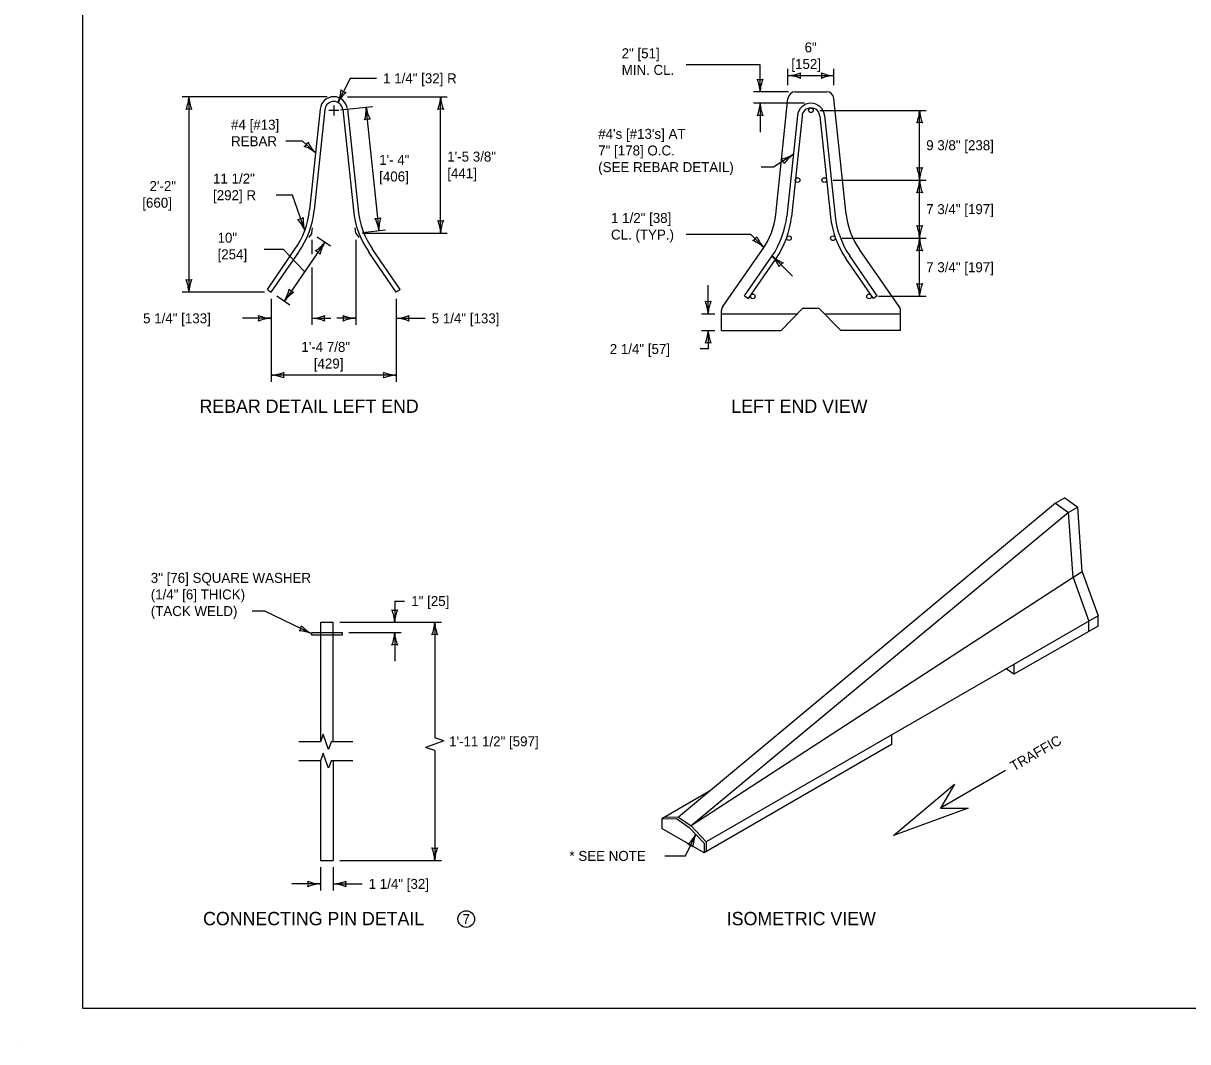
# Model space of a CAD drawing. Extents: x 49991.4 to 50021, y 49987.6 to 50011.4.
# Drawn here: x 49999.02 to 50006.04, y 49987.6 to 49993.73 of the extents above; entities that cross this region are included whole.
import ezdxf

# ---------------------------------------------------------------- set-up
doc = ezdxf.new("R2010")
doc.units = 0
for name, color, linetype in [('Level 1', 7, 'Continuous'), ('Level 2', 7, 'Continuous'), ('Level 3', 7, 'Continuous'), ('Level 4', 7, 'Continuous'), ('Level 6', 7, 'Continuous')]:
    doc.layers.add(name, color=color, linetype=linetype)

msp = doc.modelspace()

# ---------------------------------------------------------------- linework, layer by layer
at = {"layer": 'Level 1'}
for p, q in [((50003.5549, 49992.5777), (50003.6287, 49993.2762)), ((50003.6726, 49993.3157), (50003.8618, 49993.3157)), ((50003.9796, 49992.5777), (50003.9058, 49993.2762)), ((50000.8121, 49993.2116), (50000.7483, 49992.6061)), ((50000.8402, 49993.2089), (50000.7764, 49992.6032)), ((50000.948, 49993.2089), (50001.0118, 49992.6032)), ((50000.9762, 49993.2116), (50001.0399, 49992.6061)), ((50003.6852, 49993.1724), (50003.6215, 49992.5668)), ((50003.7133, 49993.1696), (50003.6496, 49992.5639)), ((50003.8211, 49993.1696), (50003.8849, 49992.5639)), ((50003.8493, 49993.1724), (50003.913, 49992.5669)), ((50000.4945, 49992.1265), (50000.6603, 49992.3677)), ((50001.2936, 49992.1265), (50001.1279, 49992.3677)), ((50003.2359, 49992.024), (50003.4758, 49992.3662)), ((50004.2985, 49992.024), (50004.0587, 49992.3662)), ((50000.5177, 49992.1104), (50000.6836, 49992.3516)), ((50001.2703, 49992.1104), (50001.1046, 49992.3516)), ((50003.3677, 49992.0871), (50003.5334, 49992.3283)), ((50003.391, 49992.0711), (50003.5567, 49992.3124)), ((50004.1436, 49992.0711), (50003.9777, 49992.3124)), ((50004.1667, 49992.0871), (50004.001, 49992.3284)), ((50000.4945, 49992.1265), (50000.5177, 49992.1104)), ((50001.2936, 49992.1265), (50001.2703, 49992.1104)), ((50003.3677, 49992.0871), (50003.391, 49992.0711)), ((50004.1667, 49992.0871), (50004.1436, 49992.0711)), ((50003.5868, 49991.8782), (50003.7191, 49992.0126)), ((50003.7191, 49992.0126), (50003.8152, 49992.0126)), ((50003.9475, 49991.8782), (50003.8152, 49992.0126)), ((50003.2279, 49991.8782), (50003.2279, 49991.9986)), ((50004.3064, 49991.8782), (50004.3065, 49991.9986)), ((50003.2279, 49991.8782), (50003.5868, 49991.8782)), ((50004.3064, 49991.8782), (50003.9475, 49991.8782)), ((50005.2397, 49990.8408), (50002.9697, 49988.9511)), ((50005.2953, 49990.8729), (50005.2397, 49990.8408)), ((50005.2397, 49990.8408), (50005.3181, 49990.7846)), ((50005.2953, 49990.8729), (50005.3736, 49990.8168)), ((50005.3181, 49990.7846), (50003.0452, 49988.897)), ((50005.3736, 49990.8168), (50005.3181, 49990.7846)), ((50005.3451, 49990.3934), (50005.3181, 49990.7846)), ((50005.4006, 49990.4264), (50005.3736, 49990.8168)), ((50005.4006, 49990.4264), (50005.3451, 49990.3934)), ((50005.4006, 49990.4264), (50005.4957, 49990.1624)), ((50005.3451, 49990.3934), (50003.0452, 49988.897)), ((50005.3451, 49990.3934), (50005.4402, 49990.1304)), ((50000.8143, 49990.1227), (50000.8143, 49989.4034)), ((50000.8905, 49990.1227), (50000.8143, 49990.1227)), ((50000.8905, 49989.4034), (50000.8905, 49990.1227)), ((50005.4957, 49990.1624), (50003.1363, 49988.8014)), ((50005.4402, 49990.0674), (50005.4402, 49990.1304)), ((50005.4957, 49990.0989), (50005.4957, 49990.1624)), ((50000.7611, 49990.0618), (50000.9439, 49990.0618)), ((50000.7611, 49990.0465), (50000.7611, 49990.0618)), ((50000.9439, 49990.0465), (50000.7611, 49990.0465)), ((50000.9439, 49990.0618), (50000.9439, 49990.0465)), ((50005.4957, 49990.0989), (50004.9887, 49989.8113)), ((50004.9887, 49989.8113), (50004.9434, 49989.8438)), ((50004.9887, 49989.87), (50004.9887, 49989.8113)), ((50004.2529, 49989.4455), (50004.2529, 49989.3874)), ((50004.2529, 49989.3874), (50003.1233, 49988.7352)), ((50000.8143, 49989.29), (50000.8143, 49988.6899)), ((50000.8905, 49989.29), (50000.8905, 49988.6899)), ((50004.9391, 49989.2312), (50004.5477, 49989.0052)), ((50004.9393, 49989.2308), (50004.5479, 49989.0049)), ((50003.1563, 49989.1065), (50002.869, 49988.9406)), ((50002.869, 49988.9406), (50002.9584, 49988.9417)), ((50002.869, 49988.9406), (50002.869, 49988.882)), ((50002.9697, 49988.9511), (50002.8827, 49988.9485)), ((50002.9584, 49988.9417), (50003.034, 49988.8875)), ((50002.9697, 49988.9511), (50003.0452, 49988.897)), ((50003.1233, 49988.7352), (50002.869, 49988.882)), ((50003.034, 49988.8875), (50003.1233, 49988.7938)), ((50003.0452, 49988.897), (50003.1363, 49988.8014)), ((50003.1233, 49988.7938), (50003.1233, 49988.7352)), ((50003.1363, 49988.8014), (50003.1363, 49988.7427)), ((50000.8143, 49988.6899), (50000.8905, 49988.6899)), ((49999.0245, 49987.5988), (49999.0245, 49987.5988))]:
    msp.add_line(p, q, dxfattribs=at)
for points in [[(49999.3835, 49998.9992), (50016.7501, 49998.9992), (50016.7501, 49987.7988), (49999.3835, 49987.7988)], [(50004.7147, 49989.0049), (50004.2635, 49988.8407), (50004.6311, 49989.1497), (50004.5481, 49989.005)]]:
    msp.add_lwpolyline(points, close=True, dxfattribs=at)
for centre in [(50003.7672, 49993.2044), (50003.687, 49992.7844), (50003.8475, 49992.7844), (50003.6348, 49992.4349), (50003.8997, 49992.4346), (50003.4172, 49992.0843), (50004.1174, 49992.0842)]:
    msp.add_circle(centre, 0.0141, dxfattribs=at)
for centre, radius, start, end in [((50000.8941, 49993.2036), 0.0824, 5.57877, 174.42123), ((50003.6726, 49993.2715), 0.0442, 90, 173.97247), ((50003.8618, 49993.2715), 0.0442, 6.02753, 90), ((50000.8941, 49993.2036), 0.0542, 5.57877, 174.42123), ((50003.7672, 49993.1643), 0.0824, 5.57877, 174.42123), ((50003.7672, 49993.1643), 0.0542, 5.57877, 174.42123), ((50000.2348, 49992.6602), 0.5163, 325.491, 353.991), ((50000.2348, 49992.6602), 0.5446, 325.491, 353.991), ((50001.5534, 49992.6602), 0.5446, 186.009, 214.509), ((50001.5534, 49992.6602), 0.5163, 186.009, 214.509), ((50003.1065, 49992.625), 0.4509, 324.97771, 353.97247), ((50004.4279, 49992.625), 0.4509, 186.02753, 215.02228), ((50003.108, 49992.6209), 0.5163, 325.47387, 353.982), ((50003.108, 49992.6209), 0.5446, 325.491, 353.991), ((50004.4265, 49992.6209), 0.5446, 186.009, 214.509), ((50004.4265, 49992.6209), 0.5163, 186.009, 214.509), ((50003.2721, 49991.9986), 0.0442, 144.97771, 180), ((50004.2623, 49991.9986), 0.0442, 0, 35.02229)]:
    msp.add_arc(centre, radius, start, end, dxfattribs=at)
at = {"layer": 'Level 2'}
msp.add_ellipse((50001.6917, 49988.3367), major_axis=(0.05, 0), ratio=0.9994, dxfattribs=at)
at = {"layer": 'Level 3'}
for p, q in [((50003.4611, 49993.4777), (50003.0164, 49993.4777)), ((50003.4611, 49993.3157), (50003.4611, 49993.4777)), ((50003.6287, 49993.3557), (50003.6287, 49993.4532)), ((50003.6287, 49993.4132), (50003.9058, 49993.4132)), ((50003.9058, 49993.3557), (50003.9058, 49993.4532)), ((50000.9929, 49993.3968), (50000.9188, 49993.2518)), ((50001.1509, 49993.3968), (50000.9929, 49993.3968)), ((50000.8541, 49993.2861), (49999.9815, 49993.2861)), ((50000.0215, 49993.2861), (50000.0215, 49992.1104)), ((50000.9764, 49993.2861), (50001.5774, 49993.2861)), ((50001.5374, 49992.4655), (50001.5374, 49993.2861)), ((50003.6326, 49993.3157), (50003.4211, 49993.3157)), ((50000.9241, 49993.2036), (50000.8641, 49993.2036)), ((50000.8941, 49993.2336), (50000.8941, 49993.1736)), ((50000.9339, 49993.2078), (50001.1282, 49993.2283)), ((50001.1665, 49992.4803), (50001.0885, 49993.2241)), ((50003.7273, 49993.2468), (50003.4211, 49993.2468)), ((50003.4611, 49993.2468), (50003.4611, 49993.0734)), ((50003.8214, 49993.2042), (50004.4611, 49993.2042)), ((50004.4211, 49992.7844), (50004.4211, 49993.2042)), ((50000.7058, 49993.0182), (50000.6051, 49993.0182)), ((50000.7058, 49993.0182), (50000.7844, 49992.9494)), ((50003.6606, 49992.9384), (50003.5407, 49992.8626)), ((50003.5407, 49992.8626), (50003.4669, 49992.8626)), ((50003.9017, 49992.7844), (50004.4611, 49992.7844)), ((50004.4211, 49992.4349), (50004.4211, 49992.7844)), ((50000.6453, 49992.6935), (50000.5476, 49992.6935)), ((50000.7192, 49992.4814), (50000.6453, 49992.6935)), ((50000.7626, 49992.4655), (50000.7446, 49992.4395)), ((50000.7626, 49992.4655), (50000.7658, 49992.4962)), ((50000.7948, 49992.4429), (50000.8737, 49992.3887)), ((50001.0262, 49992.4655), (50001.023, 49992.4962)), ((50001.0262, 49992.4655), (50001.0442, 49992.4395)), ((50001.066, 49992.4696), (50001.2063, 49992.4845)), ((50001.0662, 49992.4655), (50001.5774, 49992.4655)), ((50003.4055, 49992.4563), (50003.0165, 49992.4563)), ((50003.4838, 49992.378), (50003.4055, 49992.4563)), ((50003.9547, 49992.4349), (50004.4611, 49992.4349)), ((50004.4211, 49992.0852), (50004.4211, 49992.4349)), ((50000.8407, 49992.4114), (50000.5965, 49992.0562)), ((50000.7626, 49992.4255), (50000.7626, 49992.3378)), ((50001.0262, 49992.4255), (50001.0262, 49991.9126)), ((50003.5334, 49992.3284), (50003.6561, 49992.2058)), ((50000.7625, 49992.2576), (50000.7626, 49991.9126)), ((50003.1481, 49991.9789), (50003.1481, 49992.1523)), ((50000.4777, 49992.1104), (49999.9815, 49992.1104)), ((50000.5506, 49992.0877), (50000.6295, 49992.0336)), ((50004.1739, 49992.0852), (50004.4611, 49992.0852)), ((50000.5177, 49992.0704), (50000.5177, 49991.5704)), ((50001.2703, 49992.0704), (50001.2703, 49991.5704)), ((50000.5177, 49991.9526), (50000.3443, 49991.9526)), ((50000.7626, 49991.9526), (50000.876, 49991.9526)), ((50001.0262, 49991.9526), (50000.9128, 49991.9526)), ((50001.2703, 49991.9526), (50001.4438, 49991.9526)), ((50003.1081, 49991.9789), (50003.1879, 49991.9789)), ((50003.1081, 49991.8782), (50003.1879, 49991.8782)), ((50003.1481, 49991.8782), (50003.1481, 49991.7679)), ((50003.1481, 49991.7679), (50003.1002, 49991.7679)), ((50001.2703, 49991.6104), (50000.5177, 49991.6104)), ((50000.4787, 49990.1904), (50000.4033, 49990.1904)), ((50000.7611, 49990.0541), (50000.4787, 49990.1904)), ((50001.2607, 49990.2507), (50001.2607, 49990.1228)), ((50001.2607, 49990.2507), (50001.3207, 49990.2507)), ((50000.9305, 49990.1228), (50001.5421, 49990.1228)), ((50001.5021, 49990.1228), (50001.5021, 49989.4286)), ((50000.9839, 49990.0618), (50001.3007, 49990.0618)), ((50001.2607, 49990.0618), (50001.2607, 49989.8884)), ((50001.5567, 49989.4092), (50001.5021, 49989.4286)), ((50001.5021, 49989.3898), (50001.4471, 49989.3703)), ((50001.5021, 49989.3509), (50001.4471, 49989.3703)), ((50001.5567, 49989.4092), (50001.5021, 49989.3898)), ((50001.5021, 49989.3509), (50001.5021, 49988.6899)), ((50003.0116, 49988.717), (50003.073, 49988.8466)), ((50002.8864, 49988.7171), (50003.0114, 49988.7171)), ((50000.8143, 49988.6499), (50000.8143, 49988.5086)), ((50000.8905, 49988.6499), (50000.8905, 49988.5086)), ((50000.9305, 49988.6899), (50001.5421, 49988.6899)), ((50000.8143, 49988.5486), (50000.6409, 49988.5486)), ((50000.8905, 49988.5486), (50001.064, 49988.5486))]:
    msp.add_line(p, q, dxfattribs=at)
msp.add_lwpolyline([(50000.7187, 49992.2338), (50000.5922, 49992.3675), (50000.4746, 49992.3675)], dxfattribs=at)
for centre, radius, start, end in [((50003.6172, 49993.6459), 0.233, 272.82731, 292.07716), ((50003.6195, 49993.191), 0.2224, 67.45601, 87.63952), ((50003.7569, 49993.4132), 0.0548, 162.13882, 197.86118), ((50003.915, 49993.6353), 0.2223, 247.45601, 267.63952), ((50003.7776, 49993.4132), 0.0548, 342.13882, 17.86118), ((50003.9173, 49993.1804), 0.233, 92.82731, 112.07716), ((50003.4611, 49993.444), 0.0548, 252.13882, 287.86118), ((50003.2284, 49993.3043), 0.233, 2.82731, 22.07716), ((50003.6832, 49993.3066), 0.2223, 157.45601, 177.63952), ((49999.7994, 49993.2952), 0.2223, 337.45601, 357.63952), ((50000.2542, 49993.2976), 0.233, 182.82731, 202.07716), ((50000.7064, 49993.3475), 0.233, 335.75871, 355.00856), ((50001.1125, 49993.1426), 0.2223, 130.38741, 150.57092), ((50000.9772, 49993.366), 0.0548, 225.07022, 260.79258), ((50001.3153, 49993.2952), 0.2223, 337.45601, 357.63952), ((50001.7701, 49993.2976), 0.233, 182.82731, 202.07716), ((50000.0215, 49993.1579), 0.0548, 72.13882, 107.86118), ((50000.8666, 49993.21), 0.2223, 343.45212, 3.63563), ((50001.3187, 49993.2598), 0.233, 188.82342, 208.07327), ((50001.5374, 49993.1579), 0.0548, 72.13882, 107.86118), ((50003.2389, 49993.2559), 0.2223, 337.45601, 357.63952), ((50003.6938, 49993.2583), 0.233, 182.82731, 202.07716), ((50004.1989, 49993.2133), 0.2223, 337.45601, 357.63952), ((50004.6538, 49993.2157), 0.233, 182.82731, 202.07716), ((50001.1019, 49993.0966), 0.0548, 78.13493, 113.85729), ((50003.4611, 49993.1186), 0.0548, 72.13882, 107.86118), ((50004.4211, 49993.076), 0.0548, 72.13882, 107.86118), ((50000.688, 49993.0339), 0.0548, 300.91368, 336.63604), ((50000.9377, 49993.1104), 0.2223, 206.23087, 226.41438), ((50000.6397, 49992.7668), 0.233, 51.60217, 70.85202), ((50003.5494, 49993.1312), 0.2226, 279.78429, 299.9678), ((50003.7949, 49992.7477), 0.2333, 125.15559, 144.40544), ((50003.5521, 49992.8698), 0.0548, 14.4671, 50.18946), ((50004.4211, 49992.9126), 0.0548, 252.13882, 287.86118), ((50004.1884, 49992.7729), 0.233, 2.82731, 22.07716), ((50004.6432, 49992.7752), 0.2223, 157.45601, 177.63952), ((50004.1989, 49992.7935), 0.2223, 337.45601, 357.63952), ((50004.6538, 49992.7959), 0.233, 182.82731, 202.07716), ((50004.4211, 49992.6562), 0.0548, 72.13882, 107.86118), ((50000.6765, 49992.6023), 0.0548, 271.61167, 307.33403), ((50000.5036, 49992.393), 0.233, 22.30016, 41.55001), ((50000.9317, 49992.5468), 0.2223, 176.92886, 197.11237), ((50001.1531, 49992.6078), 0.0548, 258.1469, 293.86927), ((50000.9363, 49992.4445), 0.233, 8.8354, 28.08525), ((50001.3884, 49992.4944), 0.2223, 163.4641, 183.6476), ((50001.5374, 49992.5937), 0.0548, 252.13882, 287.86118), ((50001.3047, 49992.454), 0.233, 2.82731, 22.07716), ((50001.7595, 49992.4563), 0.2223, 157.45601, 177.63952), ((50004.4211, 49992.5631), 0.0548, 252.13882, 287.86118), ((50004.1884, 49992.4234), 0.233, 2.82731, 22.07716), ((50004.6432, 49992.4257), 0.2223, 157.45601, 177.63952), ((50003.3931, 49992.4687), 0.0548, 297.13882, 332.86118), ((50003.6473, 49992.5286), 0.2223, 202.45601, 222.63952), ((50004.1989, 49992.444), 0.2223, 337.45601, 357.63952), ((50004.6538, 49992.4464), 0.233, 182.82731, 202.07716), ((50000.663, 49992.5449), 0.2223, 302.89881, 323.08232), ((50001.0389, 49992.2888), 0.233, 148.27011, 167.51996), ((50003.3273, 49992.2054), 0.233, 47.82731, 67.07716), ((50004.4211, 49992.3067), 0.0548, 72.13882, 107.86118), ((50000.768, 49992.3058), 0.0548, 37.58162, 73.30398), ((50003.3699, 49992.1778), 0.2223, 22.45601, 42.63952), ((50003.6899, 49992.501), 0.233, 227.82731, 247.07716), ((50003.6241, 49992.2377), 0.0548, 117.13882, 152.86118), ((50000.0215, 49992.2386), 0.0548, 252.13882, 287.86118), ((49999.7888, 49992.0989), 0.233, 2.82731, 22.07716), ((50000.2437, 49992.1012), 0.2223, 157.45601, 177.63952), ((50004.4211, 49992.2134), 0.0548, 252.13882, 287.86118), ((50004.1884, 49992.0737), 0.233, 2.82731, 22.07716), ((50004.6432, 49992.076), 0.2223, 157.45601, 177.63952), ((50000.3982, 49992.1785), 0.233, 328.33003, 347.57988), ((50000.7744, 49991.9228), 0.2223, 122.95873, 143.14224), ((50000.6691, 49992.1619), 0.0548, 217.64154, 253.3639), ((50003.1481, 49992.1071), 0.0548, 252.13882, 287.86118), ((50002.9154, 49991.9674), 0.233, 2.82731, 22.07716), ((50003.3702, 49991.9697), 0.2223, 157.45601, 177.63952), ((50000.5269, 49992.1747), 0.2223, 247.45601, 267.63952), ((50000.3895, 49991.9526), 0.0548, 342.13882, 17.86118), ((50000.5292, 49991.7199), 0.233, 92.82731, 112.07716), ((50000.7535, 49992.1747), 0.2223, 272.36048, 292.54399), ((50000.7511, 49991.7199), 0.233, 67.92284, 87.17269), ((50000.8908, 49991.9526), 0.0548, 162.13882, 197.86118), ((50000.898, 49991.9526), 0.0548, 342.13882, 17.86118), ((50001.0377, 49992.1853), 0.233, 247.92284, 267.17269), ((50001.0354, 49991.7305), 0.2223, 92.36048, 112.54399), ((50001.2588, 49992.1853), 0.233, 272.82731, 292.07716), ((50001.2612, 49991.7305), 0.2223, 67.45601, 87.63952), ((50001.3985, 49991.9526), 0.0548, 162.13882, 197.86118), ((50002.9259, 49991.8873), 0.2223, 337.45601, 357.63952), ((50003.3808, 49991.8897), 0.233, 182.82731, 202.07716), ((50003.1481, 49991.75), 0.0548, 72.13882, 107.86118), ((50000.5062, 49991.8431), 0.233, 272.82731, 292.07716), ((50000.5086, 49991.3883), 0.2223, 67.45601, 87.63952), ((50000.6459, 49991.6104), 0.0548, 162.13882, 197.86118), ((50001.2795, 49991.8325), 0.2223, 247.45601, 267.63952), ((50001.1421, 49991.6104), 0.0548, 342.13882, 17.86118), ((50001.2818, 49991.3777), 0.233, 92.82731, 112.07716), ((50001.2607, 49990.251), 0.0548, 252.13882, 287.86118), ((50001.028, 49990.1113), 0.233, 2.82731, 22.07716), ((50001.4828, 49990.1136), 0.2223, 157.45601, 177.63952), ((50001.2799, 49990.1318), 0.2223, 337.45601, 357.63952), ((50001.7348, 49990.1342), 0.233, 182.82731, 202.07716), ((50000.6456, 49990.1098), 0.0548, 316.3746, 352.09696), ((50000.6703, 49989.8395), 0.233, 67.06309, 86.31294), ((50000.8659, 49990.2502), 0.2223, 221.69179, 241.8753), ((50001.0386, 49990.071), 0.2223, 337.45601, 357.63952), ((50001.4934, 49990.0733), 0.233, 182.82731, 202.07716), ((50001.5021, 49989.9945), 0.0548, 72.13882, 107.86118), ((50001.2607, 49989.9336), 0.0548, 72.13882, 107.86118), ((50001.5021, 49988.8181), 0.0548, 252.13882, 287.86118), ((50001.2693, 49988.6784), 0.233, 2.82731, 22.07716), ((50001.7242, 49988.6807), 0.2223, 157.45601, 177.63952), ((50000.8235, 49988.7707), 0.2223, 247.45601, 267.63952), ((50000.6861, 49988.5486), 0.0548, 342.13882, 17.86118), ((50000.8258, 49988.3159), 0.233, 92.82731, 112.07716), ((50000.879, 49988.7813), 0.233, 272.82731, 292.07716), ((50000.8814, 49988.3264), 0.2223, 67.45601, 87.63952), ((50001.0187, 49988.5486), 0.0548, 162.13882, 197.86118)]:
    msp.add_arc(centre, radius, start, end, dxfattribs=at)
for centre, major_axis, start_param, end_param in [((50002.8762, 49988.95), (0.2009, -0.0953), 5.889525, 6.241794), ((50003.0183, 49988.7313), (0.0495, -0.0235), 1.258867, 1.88234), ((50003.2882, 49988.7571), (-0.2105, 0.0998), 0.049153, 0.385126)]:
    msp.add_ellipse(centre, major_axis=major_axis, ratio=0.995323, start_param=start_param, end_param=end_param, dxfattribs=at)
at = {"layer": 'Level 4'}
for p, q in [((50003.2279, 49991.9789), (50003.6859, 49991.9789)), ((50003.8483, 49991.9789), (50004.3065, 49991.9789))]:
    msp.add_line(p, q, dxfattribs=at)
at = {"layer": 'Level 6'}
for p, q in [((50000.8305, 49989.4492), (50000.8143, 49989.4035)), ((50000.8467, 49989.4035), (50000.8305, 49989.4492)), ((50000.8143, 49989.4034), (50000.6843, 49989.4036)), ((50000.8629, 49989.3578), (50000.8467, 49989.4035)), ((50000.8791, 49989.4034), (50000.8629, 49989.3578)), ((50001.0091, 49989.4032), (50000.8791, 49989.4034)), ((50000.8143, 49989.29), (50000.6843, 49989.2902)), ((50000.8305, 49989.3358), (50000.8143, 49989.2901)), ((50000.8467, 49989.2901), (50000.8305, 49989.3358)), ((50000.8629, 49989.2444), (50000.8467, 49989.2901)), ((50000.8791, 49989.29), (50000.8629, 49989.2444)), ((50001.0091, 49989.2898), (50000.8791, 49989.29))]:
    msp.add_line(p, q, dxfattribs=at)

# ---------------------------------------------------------------- texts
at = {"layer": 'Level 2'}
for s, height, p in [('2" [51]', 0.06, (50002.6273, 49993.5177)), ('6"', 0.06, (50003.7289, 49993.5532)), ('[152]', 0.06, (50003.6491, 49993.4532)), ('1 1/4" [32] R', 0.06, (50001.1909, 49993.3668)), ('MIN. CL.', 0.06, (50002.6273, 49993.4177)), ('#4 [#13] ', 0.06, (50000.2756, 49993.0882)), ("#4's [#13's] AT ", 0.06, (50002.4863, 49993.0326)), ('REBAR', 0.06, (50000.2756, 49992.9882)), ('7" [178] O.C.', 0.06, (50002.4863, 49992.9326)), ('9 3/8" [238]', 0.06, (50004.4611, 49992.9643)), ('1\'- 4"', 0.06, (50001.1673, 49992.8761)), ('1\'-5 3/8"', 0.06, (50001.5774, 49992.8958)), ('[441]', 0.06, (50001.5774, 49992.7958)), ('(SEE REBAR DETAIL)', 0.06, (50002.4863, 49992.8326)), ('11 1/2" ', 0.06, (50000.1672, 49992.7635)), ('[406]', 0.06, (50001.1673, 49992.7761)), ('2\'-2"', 0.06, (49999.7846, 49992.7182)), ('[292] R', 0.06, (50000.1672, 49992.6635)), ('[660]', 0.06, (49999.7411, 49992.6182)), ('7 3/4" [197]', 0.06, (50004.4611, 49992.5796)), ('1 1/2" [38]', 0.06, (50002.5634, 49992.5263)), ('10"', 0.06, (50000.1942, 49992.4075)), ('CL. (TYP.)', 0.06, (50002.5634, 49992.4263)), ('[254]', 0.06, (50000.1942, 49992.3075)), ('7 3/4" [197]', 0.06, (50004.4611, 49992.23)), ('5 1/4" [133]', 0.06, (49999.7459, 49991.9226)), ('5 1/4" [133]', 0.06, (50001.4838, 49991.9226)), ('1\'-4 7/8"', 0.06, (50000.6988, 49991.7504)), ('2 1/4" [57]', 0.06, (50002.5556, 49991.7379)), ('[429]', 0.06, (50000.7738, 49991.6504)), ('REBAR DETAIL LEFT END', 0.08, (50000.0857, 49991.3836)), ('LEFT END VIEW', 0.08, (50003.2875, 49991.3836)), ('3" [76] SQUARE WASHER ', 0.06, (49999.7921, 49990.3604)), ('(1/4" [6] THICK)', 0.06, (49999.7921, 49990.2604)), ('1" [25]', 0.06, (50001.3607, 49990.2207)), ('(TACK WELD)', 0.06, (49999.7921, 49990.1604)), ('1\'-11 1/2" [597]', 0.06, (50001.5886, 49989.3763)), ('* SEE NOTE', 0.06, (50002.3131, 49988.6871)), ('1 1/4" [32]', 0.06, (50001.104, 49988.5186)), ('CONNECTING PIN DETAIL', 0.08, (50000.1071, 49988.2999)), ('7', 0.06, (50001.6693, 49988.3067)), ('ISOMETRIC VIEW', 0.08, (50003.2604, 49988.2999))]:
    msp.add_text(s, height=height, dxfattribs=at).set_placement(p)
msp.add_text('TRAFFIC', height=0.06, rotation=30, dxfattribs=at).set_placement((50004.9889, 49989.2248))

doc.saveas('drawing.dxf')
